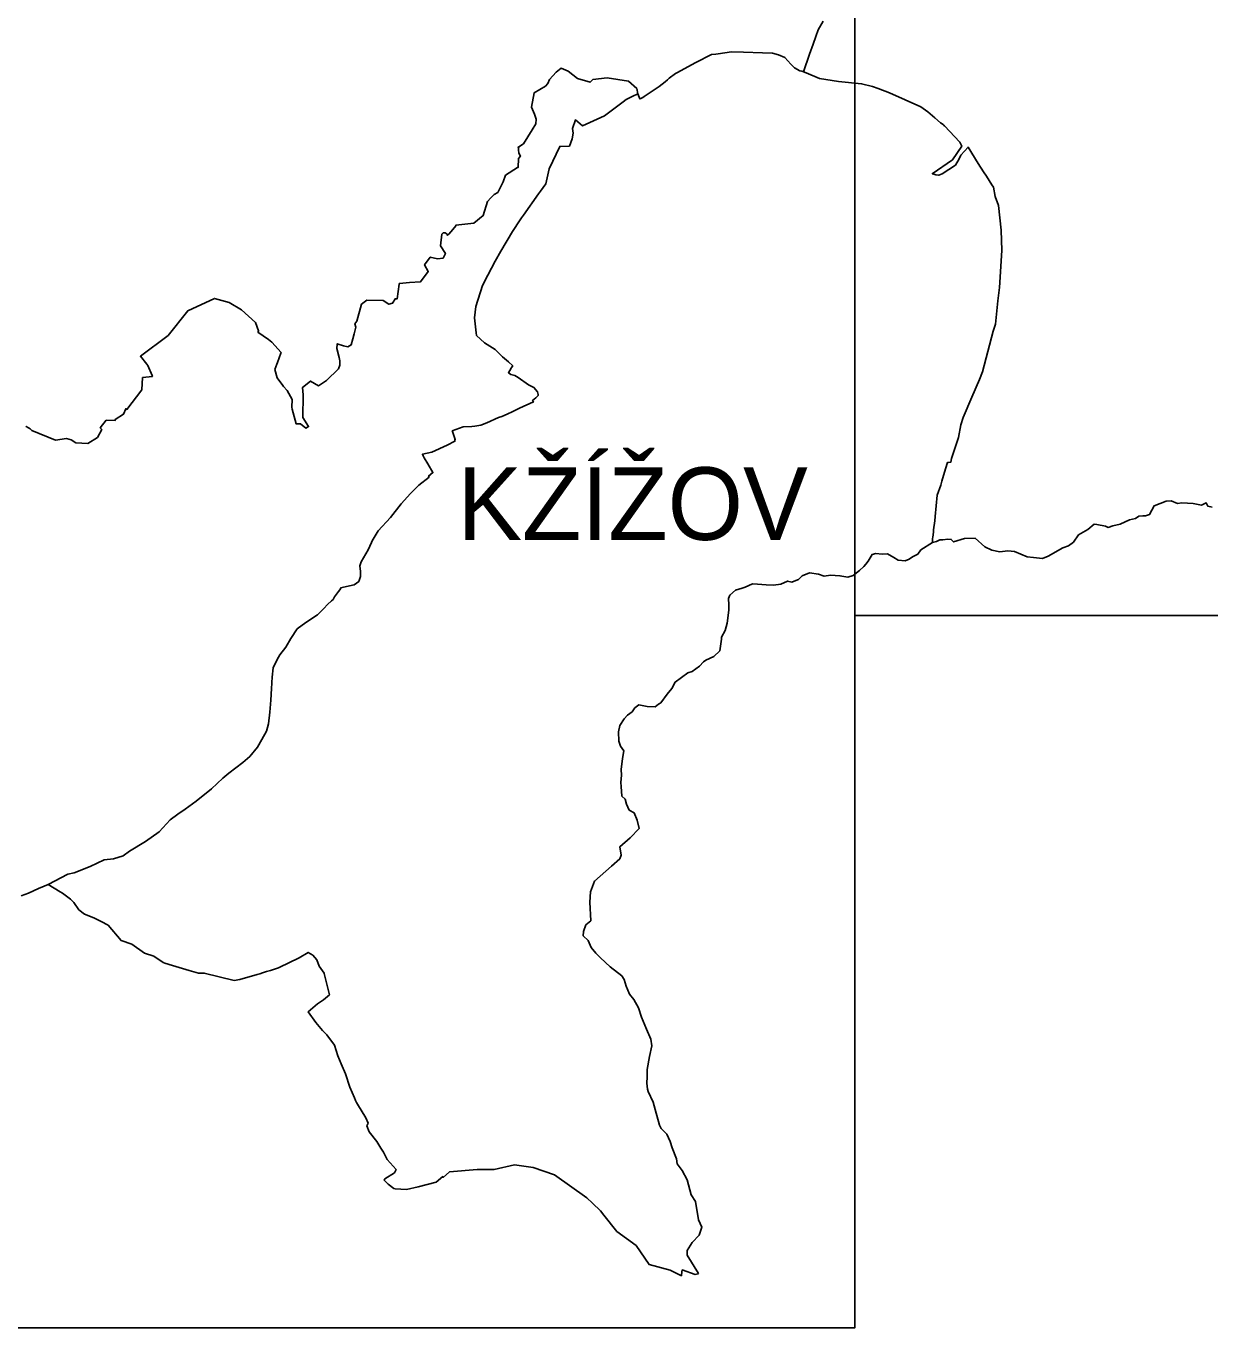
# Model space of a CAD drawing. Extents: x -547343 to -529607, y -1096298 to -1087453.
# Drawn here: x -530012.1 to -529901.2, y -1092395.7 to -1092273.7 of the extents above; entities that cross this region are included whole.
import ezdxf

# ---------------------------------------------------------------- set-up
doc = ezdxf.new("R2010")
doc.units = 0
doc.layers.add('Vrstva 18', color=7, linetype='Continuous')
doc.layers.add('Vrstva 9', color=7, linetype='Continuous')

msp = doc.modelspace()

# ---------------------------------------------------------------- linework, layer by layer
at = {"layer": 'Vrstva 18'}
for points in [[(-529847.33, -1092156.74), (-529847.33, -1092328.92), (-529934.49, -1092328.92), (-529934.49, -1092156.74)], [(-529934.49, -1092213.33), (-529934.49, -1092395.65), (-530021.66, -1092395.65), (-530021.66, -1092213.33)]]:
    msp.add_lwpolyline(points, close=True, dxfattribs=at)
for points in [[(-529939.29, -1092277.99), (-529938.74, -1092276.34), (-529938.4, -1092275.4), (-529938.13, -1092274.68), (-529937.91, -1092274.07), (-529937.46, -1092273.24)], [(-529927.21, -1092322.08), (-529927.2, -1092322.01), (-529927.2, -1092321.78), (-529927.2, -1092321.72), (-529927.18, -1092321.59), (-529927.13, -1092321.11), (-529927.11, -1092320.89), (-529927.01, -1092320.04), (-529926.97, -1092319.64), (-529926.77, -1092317.65), (-529926.43, -1092316.71), (-529926.33, -1092316.35), (-529926, -1092315.17), (-529925.82, -1092314.6), (-529925.71, -1092314.58), (-529925.51, -1092314.56), (-529925.43, -1092314.2), (-529925.32, -1092313.85), (-529924.77, -1092312.24), (-529924.56, -1092311.07), (-529924.34, -1092310.38), (-529923.54, -1092308.48), (-529922.8, -1092306.8), (-529922.52, -1092306.11), (-529921.52, -1092302.3), (-529921.32, -1092301.62), (-529921.08, -1092299.44), (-529920.95, -1092298.19), (-529920.72, -1092294.74), (-529920.78, -1092292.82), (-529921.02, -1092290.52), (-529921.35, -1092289.68), (-529921.5, -1092288.81), (-529921.65, -1092288.59), (-529922.17, -1092287.78), (-529922.43, -1092287.35), (-529922.93, -1092286.57), (-529923.88, -1092285.05), (-529924.57, -1092285.79), (-529924.72, -1092286.16), (-529925.07, -1092286.74), (-529926.3, -1092287.56), (-529926.63, -1092287.68), (-529926.89, -1092287.63), (-529927.18, -1092287.56), (-529927.24, -1092287.54), (-529925.35, -1092286.25), (-529924.48, -1092284.95), (-529924.65, -1092284.59), (-529926.08, -1092283.06), (-529926.14, -1092283.01), (-529926.19, -1092282.97), (-529926.4, -1092282.82), (-529926.46, -1092282.77), (-529927, -1092282.32), (-529927.64, -1092281.73), (-529928.31, -1092281.28), (-529931.25, -1092279.95), (-529932.31, -1092279.56), (-529932.84, -1092279.37), (-529933.85, -1092279.12), (-529936.02, -1092278.89), (-529937.8, -1092278.61), (-529939.06, -1092278.09), (-529939.29, -1092277.99), (-529939.44, -1092277.95), (-529939.48, -1092277.94), (-529939.64, -1092277.9), (-529940.14, -1092277.61), (-529940.47, -1092277.28), (-529941.06, -1092276.66), (-529941.64, -1092276.39), (-529942.19, -1092276.25), (-529943.15, -1092276.23), (-529944.93, -1092276.16), (-529946.05, -1092276.12), (-529947.28, -1092276.32), (-529947.52, -1092276.34), (-529947.91, -1092276.38), (-529949.4, -1092277.13), (-529949.78, -1092277.33), (-529951.1, -1092278.05), (-529951.3, -1092278.15), (-529951.88, -1092278.6), (-529952.03, -1092278.74), (-529952.25, -1092278.94), (-529952.81, -1092279.37), (-529954.23, -1092280.3), (-529954.36, -1092280.39), (-529954.47, -1092280.45), (-529954.55, -1092280.5), (-529954.62, -1092280.54), (-529954.82, -1092280.07), (-529954.87, -1092280.1)], [(-529954.82, -1092280.07), (-529954.91, -1092279.57), (-529955.68, -1092278.88), (-529957.7, -1092278.57), (-529959.03, -1092278.73), (-529959.29, -1092278.97), (-529960.48, -1092278.61), (-529961.36, -1092277.95), (-529962, -1092277.66), (-529962.46, -1092278.02), (-529963.09, -1092278.72), (-529963.24, -1092279.1), (-529963.48, -1092279.33), (-529964.53, -1092279.96), (-529964.79, -1092281.3), (-529964.49, -1092281.95), (-529964.33, -1092282.42), (-529964.36, -1092282.87), (-529964.73, -1092283.44), (-529965.52, -1092284.74), (-529966.05, -1092285.07), (-529965.96, -1092285.08), (-529966.01, -1092285.11), (-529965.99, -1092285.29), (-529965.96, -1092285.63), (-529965.82, -1092285.89), (-529965.99, -1092286.13), (-529966.03, -1092286.97), (-529966.09, -1092286.96), (-529967.22, -1092287.68), (-529967.44, -1092288.31), (-529967.92, -1092289.29), (-529968.27, -1092289.49), (-529968.58, -1092289.8), (-529968.89, -1092290.13), (-529969.31, -1092291.46), (-529970.19, -1092292.16), (-529971.03, -1092292.25), (-529971.86, -1092292.35), (-529971.88, -1092292.41), (-529972.16, -1092292.77), (-529972.53, -1092293.19), (-529972.68, -1092293.3), (-529972.67, -1092293.21), (-529972.88, -1092293.09), (-529973.05, -1092293.09), (-529973.17, -1092293.19), (-529973.31, -1092294.3), (-529972.84, -1092295.02), (-529973.06, -1092295.44), (-529973.6, -1092295.51), (-529974.26, -1092295.35), (-529974.79, -1092296.09), (-529974.45, -1092296.7), (-529975.17, -1092297.66), (-529976.22, -1092297.74), (-529977.16, -1092297.81), (-529977.17, -1092297.87), (-529977.26, -1092298.56), (-529977.37, -1092299.27), (-529977.48, -1092299.25), (-529977.53, -1092299.23), (-529977.8, -1092299.67), (-529978.14, -1092299.76), (-529978.68, -1092299.42), (-529980.21, -1092299.37), (-529980.7, -1092299.76), (-529981.15, -1092301.36), (-529981.34, -1092301.59), (-529981.23, -1092301.9), (-529981.4, -1092302.55), (-529981.53, -1092303.01), (-529981.68, -1092303.58), (-529981.98, -1092303.75), (-529982.4, -1092303.66), (-529982.98, -1092303.46), (-529982.98, -1092303.5), (-529983.02, -1092303.91), (-529982.8, -1092304.74), (-529982.73, -1092305.08), (-529982.73, -1092305.47), (-529982.87, -1092305.83), (-529984, -1092306.92), (-529984.72, -1092307.4), (-529985.48, -1092306.97), (-529986.22, -1092307.56), (-529986.16, -1092308.24), (-529986.19, -1092310.38), (-529985.66, -1092311.22), (-529985.93, -1092311.36), (-529986.42, -1092310.98), (-529986.82, -1092310.98), (-529987.2, -1092309.58), (-529987.24, -1092309.42), (-529987.19, -1092308.68), (-529987.67, -1092307.85), (-529988.01, -1092307.47), (-529988.09, -1092307.38), (-529988.6, -1092306.65), (-529988.82, -1092305.87), (-529988.64, -1092305.37), (-529988.59, -1092305.22), (-529988.27, -1092304.34), (-529988.24, -1092304.28), (-529989.12, -1092303.31), (-529989.43, -1092303.08), (-529990.41, -1092302.38), (-529990.39, -1092302.34), (-529990.35, -1092302.25), (-529990.63, -1092301.47), (-529991.96, -1092300.3), (-529993.11, -1092299.61), (-529994.49, -1092299.22), (-529996.98, -1092300.39), (-529998.82, -1092302.7), (-530001.42, -1092304.64), (-530000.82, -1092305.38), (-530000.73, -1092305.5), (-530000.31, -1092306.44), (-530000.3, -1092306.53), (-530001.21, -1092306.63), (-530001.29, -1092307.77), (-530002.69, -1092309.62), (-530002.79, -1092309.56), (-530003, -1092310.07), (-530003.77, -1092310.55), (-530003.78, -1092310.64), (-530004.62, -1092310.63), (-530005.18, -1092311.35), (-530005.12, -1092311.42), (-530005.04, -1092311.5), (-530005.44, -1092312.26), (-530006.35, -1092312.8), (-530007.46, -1092312.75), (-530007.91, -1092312.47), (-530008.33, -1092312.34), (-530009.37, -1092312.51), (-530011.58, -1092311.59), (-530011.75, -1092311.45), (-530011.85, -1092311.36), (-530011.9, -1092311.33), (-530012.11, -1092311.23), (-530012.15, -1092311.2)], [(-529954.87, -1092280.1), (-529955.29, -1092280.29), (-529955.9, -1092280.59), (-529956.2, -1092280.81), (-529957.94, -1092282.13), (-529960, -1092283.05), (-529960.66, -1092282.5), (-529960.94, -1092283.31), (-529960.87, -1092283.73), (-529960.98, -1092284.28), (-529961.23, -1092284.95), (-529962.14, -1092284.98), (-529963.14, -1092287.07), (-529963.44, -1092288.5), (-529963.94, -1092289.19), (-529964.11, -1092289.43), (-529965.53, -1092291.42), (-529965.71, -1092291.66), (-529965.85, -1092291.85), (-529966.56, -1092292.94), (-529967.65, -1092294.81), (-529968.19, -1092295.74), (-529968.87, -1092297.03), (-529968.88, -1092297.05), (-529969.38, -1092298.02), (-529970.01, -1092299.97), (-529970.11, -1092301.03), (-529969.97, -1092302.43), (-529969.94, -1092302.68), (-529969.17, -1092303.38), (-529968.18, -1092304), (-529967.68, -1092304.51), (-529967.5, -1092304.69), (-529966.93, -1092305.17), (-529966.54, -1092305.52), (-529966.66, -1092305.69), (-529966.69, -1092305.76), (-529966.94, -1092306.18), (-529966.71, -1092306.36), (-529966.35, -1092306.45), (-529966.04, -1092306.63), (-529965.07, -1092307.3), (-529964.56, -1092307.56), (-529964.22, -1092307.96), (-529964.16, -1092308.23), (-529964.16, -1092308.3), (-529964.37, -1092308.52), (-529964.68, -1092308.78), (-529964.6, -1092308.92), (-529965.9, -1092309.51), (-529966.14, -1092309.63), (-529966.53, -1092309.81), (-529967.05, -1092310.06), (-529967.57, -1092310.29), (-529967.88, -1092310.37), (-529968.98, -1092310.88), (-529969.53, -1092311.09), (-529970.09, -1092311.18), (-529970.38, -1092311.21), (-529971.18, -1092311.24), (-529972.2, -1092311.61), (-529972.18, -1092311.7), (-529971.92, -1092312.44), (-529971.96, -1092312.45), (-529971.95, -1092312.6), (-529972.69, -1092312.98), (-529974.11, -1092313.61), (-529975, -1092313.82), (-529974.92, -1092313.98), (-529974.82, -1092314.15), (-529974.49, -1092314.72), (-529974.02, -1092315.54), (-529974.42, -1092315.86), (-529974.37, -1092315.95), (-529975.34, -1092316.7), (-529976.13, -1092317.49), (-529976.98, -1092318.47), (-529978, -1092319.74), (-529979.14, -1092321), (-529979.71, -1092321.94), (-529979.78, -1092322.09), (-529980.09, -1092322.78), (-529980.73, -1092323.88), (-529980.86, -1092324.27), (-529980.81, -1092324.79), (-529980.8, -1092325.26), (-529980.95, -1092325.72), (-529981.4, -1092326.04), (-529982.67, -1092326.32), (-529982.65, -1092326.39), (-529982.87, -1092326.66), (-529983.24, -1092327.18), (-529983.35, -1092327.42), (-529983.51, -1092327.56), (-529983.9, -1092327.88), (-529984.24, -1092328.26), (-529984.83, -1092328.87), (-529985.92, -1092329.57), (-529986.74, -1092330.18), (-529987.33, -1092331.08), (-529987.78, -1092331.89), (-529988.35, -1092332.61), (-529988.61, -1092333.04), (-529988.99, -1092333.83), (-529989.07, -1092334.71), (-529989.08, -1092334.86), (-529989.1, -1092335.05), (-529989.11, -1092335.25), (-529989.14, -1092335.77), (-529989.2, -1092336.84), (-529989.3, -1092337.96), (-529989.42, -1092339.07), (-529989.61, -1092339.76), (-529990.05, -1092340.53), (-529990.45, -1092341.26), (-529991.16, -1092342.12), (-529991.83, -1092342.7), (-529993.13, -1092343.69), (-529993.69, -1092344.17), (-529994.76, -1092345.16), (-529996.2, -1092346.3), (-529997.24, -1092347.06), (-529997.9, -1092347.53), (-529998.63, -1092348.06), (-529999.67, -1092349.17), (-530000.95, -1092350.1), (-530002.44, -1092350.99), (-530003.03, -1092351.42), (-530003.94, -1092351.7), (-530004.8, -1092351.81), (-530006.13, -1092352.43), (-530007.61, -1092353.01), (-530008.23, -1092353.16), (-530010.06, -1092354.13)], [(-530012.58, -1092355.19), (-530011.89, -1092354.93), (-530010.98, -1092354.5), (-530010.43, -1092354.26), (-530010.06, -1092354.13), (-530008.93, -1092354.79), (-530008.71, -1092354.92), (-530007.97, -1092355.48), (-530007.67, -1092355.81), (-530007.18, -1092356.48), (-530006.66, -1092356.89), (-530005.77, -1092357.24), (-530005.1, -1092357.57), (-530004.43, -1092357.94), (-530003.23, -1092359.37), (-530002.22, -1092359.72), (-530001.03, -1092360.55), (-530000.17, -1092360.83), (-529999.28, -1092361.41), (-529999.12, -1092361.47), (-529998.4, -1092361.71), (-529996.84, -1092362.17), (-529995.97, -1092362.42), (-529995.44, -1092362.42), (-529992.62, -1092363.1), (-529992.1, -1092363.01), (-529990.48, -1092362.55), (-529990.24, -1092362.48), (-529989.98, -1092362.4), (-529989.6, -1092362.28), (-529989.24, -1092362.16), (-529988.48, -1092361.92), (-529988.42, -1092361.9), (-529986.55, -1092360.99), (-529985.7, -1092360.47), (-529985.27, -1092360.74), (-529984.88, -1092361.17), (-529984.68, -1092361.78), (-529984.21, -1092362.42), (-529984.2, -1092362.46), (-529983.69, -1092364.44), (-529984.26, -1092364.93), (-529984.82, -1092365.29), (-529985.7, -1092366.03), (-529984.98, -1092367.04), (-529984.36, -1092367.8), (-529983.96, -1092368.19), (-529983.25, -1092369.16), (-529982.91, -1092370.17), (-529982.6, -1092370.92), (-529982.22, -1092371.84), (-529981.8, -1092373.1), (-529981.37, -1092374.1), (-529981.26, -1092374.35), (-529981.18, -1092374.52), (-529981.08, -1092374.68), (-529980.29, -1092375.96), (-529980.09, -1092376.48), (-529980.22, -1092376.72), (-529979.99, -1092377.27), (-529979.28, -1092378.19), (-529978.88, -1092378.81), (-529978.64, -1092379.2), (-529978.3, -1092379.88), (-529977.46, -1092380.82), (-529977.63, -1092381.11), (-529978.53, -1092381.7), (-529978.59, -1092381.82), (-529978.2, -1092382.17), (-529977.67, -1092382.59), (-529977.55, -1092382.61), (-529977.01, -1092382.65), (-529976.49, -1092382.68), (-529975.41, -1092382.42), (-529973.71, -1092382.01), (-529973.1, -1092381.48), (-529973.06, -1092381.56), (-529972.46, -1092381.02), (-529969.88, -1092380.82), (-529968.28, -1092380.8), (-529966.37, -1092380.37), (-529964.61, -1092380.63), (-529962.61, -1092381.32), (-529959.61, -1092383.48), (-529959.08, -1092383.95), (-529958.32, -1092384.68), (-529957.99, -1092385.09), (-529956.79, -1092386.61), (-529954.99, -1092387.94), (-529953.77, -1092389.72), (-529951.8, -1092390.24), (-529950.73, -1092390.76), (-529950.72, -1092390.69), (-529950.65, -1092390.21), (-529949.46, -1092390.66), (-529949.21, -1092390.57), (-529949.14, -1092390.54), (-529950.21, -1092388.82), (-529950.21, -1092388.39), (-529949.74, -1092387.65), (-529949.08, -1092386.96), (-529948.82, -1092386.21), (-529949.15, -1092385.52), (-529949.43, -1092383.8), (-529949.81, -1092383.17), (-529950.2, -1092381.78), (-529950.65, -1092380.9), (-529951.12, -1092380.28), (-529951.2, -1092379.82), (-529951.59, -1092378.78), (-529951.78, -1092378.18), (-529952.11, -1092377.5), (-529952.64, -1092376.97), (-529952.78, -1092376.66), (-529953.18, -1092375.18), (-529953.39, -1092374.51), (-529953.84, -1092373.49), (-529953.9, -1092373.3), (-529953.99, -1092372.73), (-529953.95, -1092372.13), (-529953.93, -1092371.46), (-529953.72, -1092370.24), (-529953.52, -1092369.23), (-529953.61, -1092368.61), (-529954.01, -1092367.68), (-529954.49, -1092366.53), (-529954.77, -1092365.66), (-529955.19, -1092364.88), (-529955.59, -1092364.4), (-529955.91, -1092363.63), (-529956.1, -1092363.02), (-529956.31, -1092362.68), (-529957.42, -1092361.83), (-529958.32, -1092360.98), (-529958.74, -1092360.56), (-529959.18, -1092360.01), (-529959.46, -1092359.36), (-529959.95, -1092358.91), (-529959.91, -1092358.52), (-529959.7, -1092357.9), (-529959.23, -1092357.51), (-529959.32, -1092355.78), (-529959.25, -1092354.81), (-529958.87, -1092353.8), (-529957.29, -1092352.39), (-529956.5, -1092351.7), (-529956.38, -1092351.38), (-529956.49, -1092350.58), (-529955.54, -1092349.74), (-529954.7, -1092348.86), (-529954.87, -1092348.08), (-529955.17, -1092347.39), (-529955.64, -1092347.14), (-529955.87, -1092346.58), (-529956.01, -1092346.11), (-529956.32, -1092345.83), (-529956.39, -1092344.94), (-529956.4, -1092344.55), (-529956.38, -1092344.21), (-529956.34, -1092343.88), (-529956.39, -1092343.34), (-529956.26, -1092342.31), (-529956.14, -1092341.61), (-529956.43, -1092341.16), (-529956.61, -1092340.68), (-529956.64, -1092339.81), (-529956.49, -1092339.22), (-529956.1, -1092338.61), (-529955.78, -1092338.27), (-529955.58, -1092338.11), (-529955.34, -1092337.93), (-529955.09, -1092337.57), (-529954.74, -1092337.3), (-529953.93, -1092337.43), (-529953.19, -1092337.47), (-529952.88, -1092337.23), (-529952.66, -1092337.1), (-529952.07, -1092336.3), (-529951.62, -1092335.77), (-529951.32, -1092335.16), (-529950.15, -1092334.3), (-529949.73, -1092334.18), (-529949.05, -1092333.66), (-529948.67, -1092333.26), (-529948.44, -1092333.09), (-529947.7, -1092332.77), (-529947.15, -1092332.23), (-529947.04, -1092331.58), (-529946.97, -1092331.14), (-529946.97, -1092330.96), (-529946.65, -1092330.34), (-529946.45, -1092329.65), (-529946.35, -1092328.91), (-529946.28, -1092328.39), (-529946.29, -1092327.92), (-529946.34, -1092327.33), (-529946.21, -1092327.02), (-529945.67, -1092326.56), (-529945.06, -1092326.37), (-529944.75, -1092326.26), (-529944.09, -1092325.96), (-529943.62, -1092325.97), (-529942.81, -1092326.05), (-529942.12, -1092326.07), (-529941.43, -1092326), (-529940.79, -1092325.69), (-529940.38, -1092325.79), (-529939.86, -1092325.59), (-529939.78, -1092325.55), (-529939.43, -1092325.22), (-529938.73, -1092324.93), (-529937.9, -1092325.05), (-529937.37, -1092325.25), (-529936.78, -1092325.15), (-529935.88, -1092325.19), (-529935.14, -1092325.33), (-529934.65, -1092325.16), (-529934.05, -1092324.72), (-529933.65, -1092324.34), (-529933.47, -1092324.12), (-529933.24, -1092323.83), (-529932.88, -1092323.2), (-529932.52, -1092323.11), (-529931.93, -1092323.18), (-529931.44, -1092323.15), (-529930.84, -1092323.5), (-529930.42, -1092323.73), (-529929.76, -1092323.81), (-529929.4, -1092323.63), (-529929.09, -1092323.43), (-529928.59, -1092323.18), (-529928.31, -1092322.78), (-529927.21, -1092322.08), (-529926.85, -1092322), (-529926.52, -1092321.84), (-529926.26, -1092321.84), (-529925.78, -1092321.77), (-529925.46, -1092321.79), (-529925.26, -1092322.03), (-529924.21, -1092321.72), (-529923.22, -1092321.67), (-529922.31, -1092322.48), (-529921.67, -1092322.81), (-529920.91, -1092322.95), (-529920.17, -1092322.85), (-529919.52, -1092322.94), (-529918.35, -1092323.42), (-529917.75, -1092323.5), (-529916.91, -1092323.59), (-529916.39, -1092323.36), (-529915, -1092322.59), (-529914.47, -1092322.38), (-529914, -1092322.04), (-529913.53, -1092321.38), (-529912.65, -1092320.88), (-529912.08, -1092320.38), (-529911.83, -1092320.4), (-529911, -1092320.55), (-529910.77, -1092320.67), (-529910.33, -1092320.51), (-529909.64, -1092320.37), (-529908.77, -1092319.96), (-529908.19, -1092319.85), (-529907.9, -1092319.63), (-529907.5, -1092319.57), (-529907.25, -1092319.58), (-529906.88, -1092319.45), (-529906.45, -1092318.65), (-529905.88, -1092318.43), (-529905.32, -1092318.2), (-529904.87, -1092318.19), (-529904.27, -1092318.42), (-529903.87, -1092318.37), (-529902.78, -1092318.44), (-529902, -1092318.6), (-529901.59, -1092318.36), (-529901.42, -1092318.68), (-529901.02, -1092318.78)]]:
    msp.add_lwpolyline(points, dxfattribs=at)
at = {"layer": 'Vrstva 9'}
for points in [[(-529847.33, -1092156.74), (-529934.49, -1092156.74), (-529934.49, -1092328.92), (-529847.33, -1092328.92)], [(-530021.66, -1092213.33), (-529934.49, -1092213.33), (-529934.49, -1092395.65), (-530021.66, -1092395.65)]]:
    msp.add_lwpolyline(points, close=True, dxfattribs=at)

# ---------------------------------------------------------------- texts
at = {"layer": 'Vrstva 18'}
msp.add_text('KŽÍŽOV', height=6.799, dxfattribs=at).set_placement((-529971.73, -1092321.84))

doc.saveas('drawing.dxf')
